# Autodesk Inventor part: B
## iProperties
Created: 2007-08
Part Number: B
Document SubType Name: Modeling
Designer: t-ikumi
Density: 1 g/cm^3
Author: t-ikumi
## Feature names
1. 押し出し1 [Extrusion]
2. 押し出し2 [Extrusion]
3. 押し出し3 [Extrusion]
4. 押し出し4 [Extrusion]
5. フィレット1 [Fillet]
6. 面取り1 [Chamfer]
7. 押し出し6 [Extrusion]
8. 押し出し5 [Extrusion]
9. 面取り2 [Chamfer]
10. 面取り3 [Chamfer]
